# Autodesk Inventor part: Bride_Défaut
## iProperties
Shininess: 64.0
Length Units: 11269
Angle Units: 11279
Time Units: 11290
Mass Units: 11283
Length Display Precision: 3
Angle Display Precision: 2
Compacted: True
Part Number: Bride_Défaut
Document SubType Name: Modeling
Created: 2006-01
Material: Par défaut
Designer: Fricot
Density: 0.0
Volumn: 0.0
Area: 0.0
PropertySet Name: Model Information
Control State: 0
Master: False
Checked Out: False
Author: Fricot
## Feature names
1. Base1
